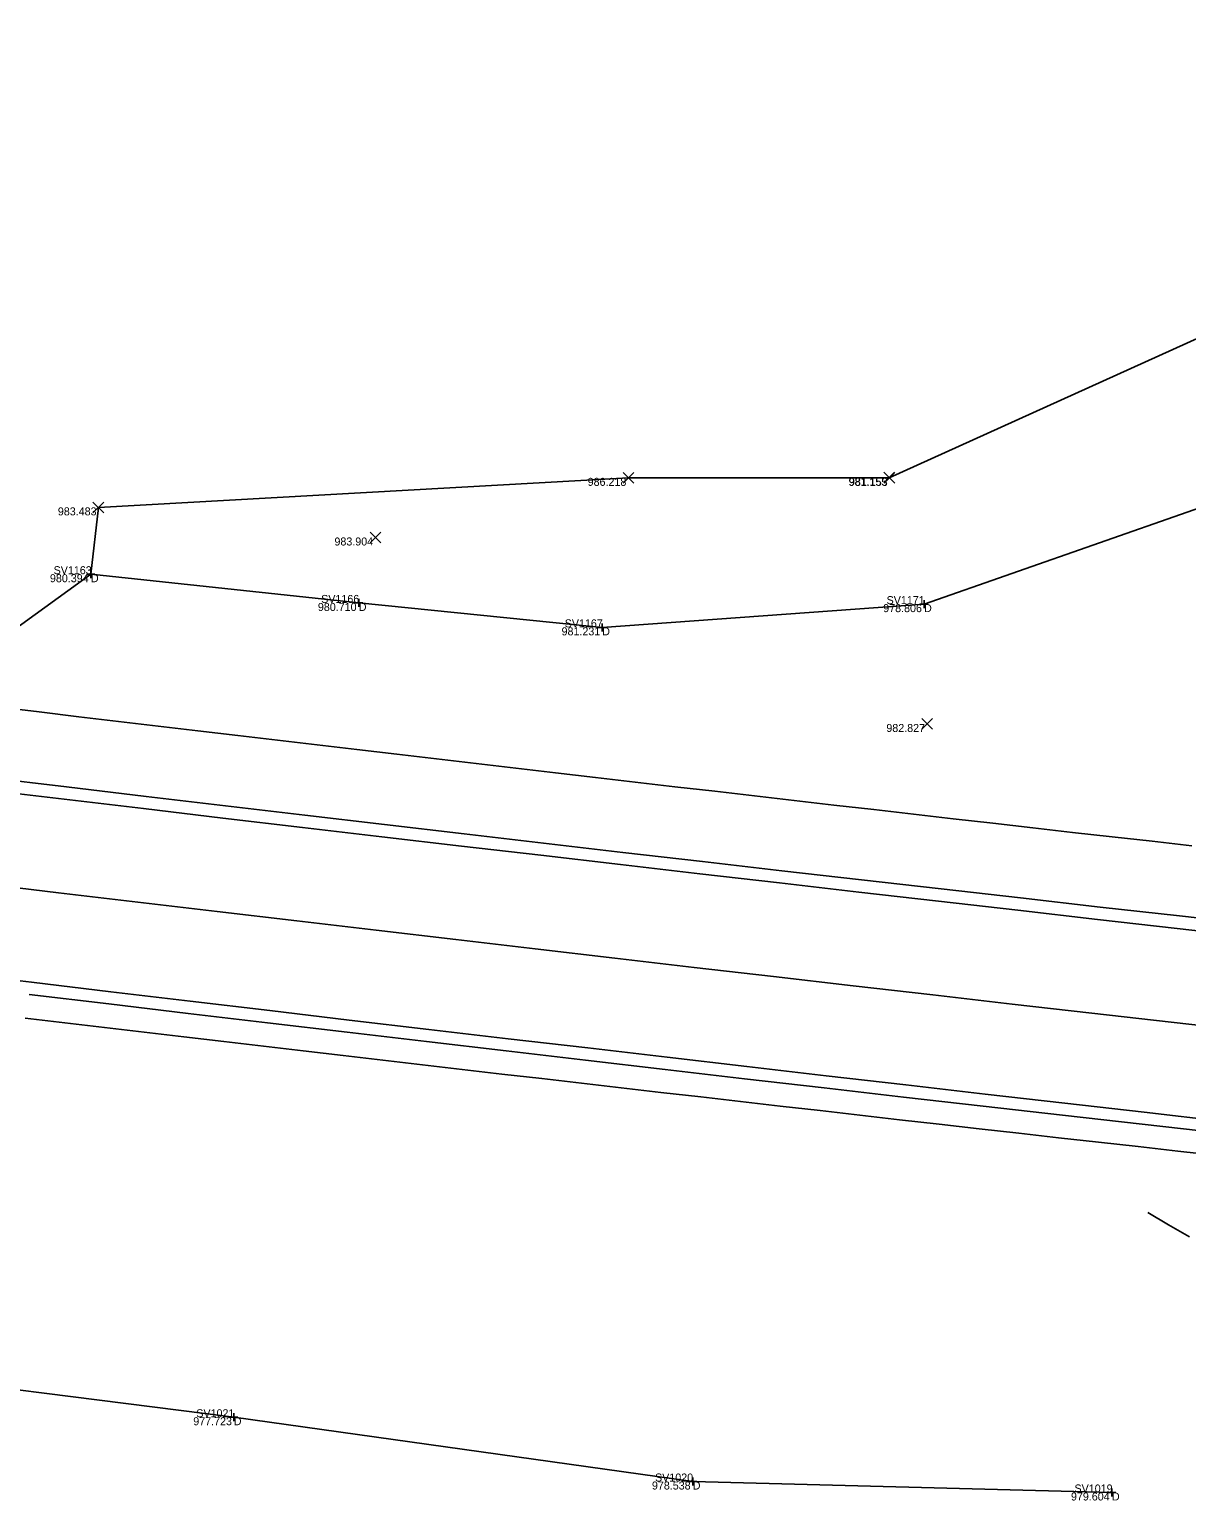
# Model space of a CAD drawing. Extents: x 2065431 to 2068157, y 709104 to 709719.
# Drawn here: x 2066972.9 to 2067117.5, y 709383.1 to 709566.9 of the extents above; entities that cross this region are included whole.
import ezdxf

# ---------------------------------------------------------------- set-up
doc = ezdxf.new("R2010")
doc.units = 0
for name, color, linetype in [('DT_X_Terrain_Boundary', 7, 'Continuous'), ('PM_X_Edge_Line', 7, 'Continuous'), ('PM_X_Lane_Line', 7, 'Continuous'), ('PV_X_EOP', 7, 'Continuous'), ('PV_X_Shoulder_Rumble_Strip', 7, 'Continuous'), ('RS_Raster1', 7, 'Continuous'), ('RW_X_CL_100_Bearings', 7, 'Continuous'), ('RW_X_Fee_WL', 7, 'Continuous'), ('SV_X_Mon_Cells_Found', 7, 'Continuous'), ('SV_X_Text_Elevation', 7, 'Continuous'), ('SV_X_Text_Name', 7, 'Continuous')]:
    doc.layers.add(name, color=color, linetype=linetype)

msp = doc.modelspace()

# ---------------------------------------------------------------- linework, layer by layer
at = {"layer": 'DT_X_Terrain_Boundary'}
msp.add_lwpolyline([(2067144.2, 709539.81), (2067080.32, 709510.92), (2067047.75, 709510.9), (2066981.51, 709507.21), (2066980.58, 709498.86), (2066959.21, 709483.43)], dxfattribs=at)
at = {"layer": 'PM_X_Edge_Line'}
for points in [[(2066967.29, 709471.93), (2066977.22, 709470.75), (2066987.15, 709469.57), (2066997.08, 709468.4), (2067007.01, 709467.22), (2067016.95, 709466.06), (2067026.88, 709464.9), (2067036.81, 709463.74), (2067046.74, 709462.58), (2067056.68, 709461.43), (2067066.61, 709460.29), (2067076.55, 709459.14), (2067086.48, 709458), (2067096.42, 709456.87), (2067106.35, 709455.74), (2067116.29, 709454.61), (2067126.22, 709453.49)], [(2066963.21, 709449.06), (2066973.14, 709447.87), (2066983.07, 709446.69), (2066993, 709445.51), (2067002.93, 709444.33), (2067012.86, 709443.16), (2067022.79, 709441.99), (2067032.72, 709440.83), (2067042.66, 709439.67), (2067052.59, 709438.51), (2067062.52, 709437.35), (2067072.46, 709436.2), (2067082.39, 709435.05), (2067092.32, 709433.91), (2067102.26, 709432.77), (2067112.19, 709431.63), (2067122.13, 709430.5)]]:
    msp.add_lwpolyline(points, dxfattribs=at)
at = {"layer": 'PM_X_Lane_Line'}
msp.add_lwpolyline([(2066966.58, 709460.24), (2066976.51, 709459.06), (2066986.44, 709457.88), (2066996.37, 709456.71), (2067006.3, 709455.54), (2067016.23, 709454.37), (2067026.16, 709453.21), (2067036.09, 709452.05), (2067046.03, 709450.89), (2067055.96, 709449.74), (2067065.89, 709448.59), (2067075.83, 709447.44), (2067085.76, 709446.3), (2067095.7, 709445.16), (2067105.63, 709444.02), (2067115.57, 709442.89), (2067125.5, 709441.77)], dxfattribs=at)
at = {"layer": 'PV_X_EOP'}
for points in [[(2066969.14, 709482.24), (2066974.1, 709481.65), (2066979.07, 709481.06), (2066984.03, 709480.47), (2066989, 709479.88), (2066993.96, 709479.29), (2066998.93, 709478.7), (2067003.89, 709478.12), (2067008.86, 709477.53), (2067013.82, 709476.95), (2067018.79, 709476.36), (2067023.76, 709475.78), (2067028.72, 709475.2), (2067033.69, 709474.62), (2067038.65, 709474.04), (2067043.62, 709473.46), (2067048.59, 709472.89), (2067053.55, 709472.31), (2067058.52, 709471.74), (2067063.49, 709471.16), (2067068.46, 709470.59), (2067073.42, 709470.02), (2067078.39, 709469.45), (2067083.36, 709468.88), (2067088.33, 709468.31), (2067093.29, 709467.74), (2067098.26, 709467.18), (2067103.23, 709466.61), (2067108.2, 709466.05), (2067113.17, 709465.49), (2067118.13, 709464.92)], [(2066972.35, 709443.41), (2066977.32, 709442.82), (2066982.28, 709442.23), (2066987.25, 709441.65), (2066992.21, 709441.06), (2066997.18, 709440.47), (2067002.14, 709439.89), (2067007.11, 709439.31), (2067012.08, 709438.73), (2067017.04, 709438.15), (2067022.01, 709437.57), (2067026.97, 709436.99), (2067031.94, 709436.41), (2067036.91, 709435.84), (2067041.88, 709435.26), (2067046.84, 709434.69), (2067051.81, 709434.12), (2067056.78, 709433.55), (2067061.74, 709432.98), (2067066.71, 709432.41), (2067071.68, 709431.84), (2067076.65, 709431.27), (2067081.61, 709430.71), (2067086.58, 709430.14), (2067091.55, 709429.58), (2067096.52, 709429.02), (2067101.49, 709428.46), (2067106.46, 709427.9), (2067111.43, 709427.34), (2067116.39, 709426.78), (2067121.36, 709426.22)], [(2067112.65, 709419.1), (2067115.24, 709417.59), (2067117.83, 709416.08)]]:
    msp.add_lwpolyline(points, dxfattribs=at)
at = {"layer": 'PV_X_Shoulder_Rumble_Strip'}
for points in [[(2066967.61, 709473.47), (2066977.54, 709472.28), (2066987.47, 709471.1), (2066997.4, 709469.93), (2067007.33, 709468.76), (2067017.26, 709467.59), (2067027.2, 709466.43), (2067037.13, 709465.27), (2067047.06, 709464.11), (2067057, 709462.96), (2067066.93, 709461.82), (2067076.86, 709460.68), (2067086.8, 709459.54), (2067096.74, 709458.41), (2067106.67, 709457.28), (2067116.61, 709456.16), (2067126.55, 709455.04)], [(2066972.87, 709446.35), (2066982.8, 709445.17), (2066992.73, 709443.98), (2067002.66, 709442.81), (2067012.59, 709441.64), (2067022.53, 709440.47), (2067032.46, 709439.3), (2067042.39, 709438.14), (2067052.32, 709436.99), (2067062.26, 709435.83), (2067072.19, 709434.69), (2067082.12, 709433.54), (2067092.06, 709432.4), (2067101.99, 709431.27), (2067111.93, 709430.13), (2067121.87, 709429.01)]]:
    msp.add_lwpolyline(points, dxfattribs=at)
at = {"layer": 'RS_Raster1'}
for p, q in [((2066980.08, 709498.86), (2066981.08, 709498.86)), ((2066980.58, 709499.36), (2066980.58, 709498.36)), ((2066980.58, 709498.86), (2066980.58, 709498.86)), ((2067013.55, 709495.27), (2067014.55, 709495.27)), ((2067014.05, 709495.77), (2067014.05, 709494.77)), ((2067014.05, 709495.27), (2067014.05, 709495.27)), ((2067084.18, 709495.12), (2067085.18, 709495.12)), ((2067084.68, 709495.62), (2067084.68, 709494.62)), ((2067084.68, 709495.12), (2067084.68, 709495.12)), ((2067044.47, 709492.72), (2067044.47, 709491.72)), ((2067043.97, 709492.22), (2067044.97, 709492.22)), ((2067044.47, 709492.22), (2067044.47, 709492.22)), ((2066997.93, 709393.53), (2066998.93, 709393.53)), ((2066998.43, 709394.03), (2066998.43, 709393.03)), ((2066998.43, 709393.53), (2066998.43, 709393.53)), ((2067055.78, 709386), (2067055.78, 709385)), ((2067055.28, 709385.5), (2067056.28, 709385.5)), ((2067055.78, 709385.5), (2067055.78, 709385.5)), ((2067107.66, 709384.13), (2067108.66, 709384.13)), ((2067108.16, 709384.63), (2067108.16, 709383.63)), ((2067108.16, 709384.13), (2067108.16, 709384.13))]:
    msp.add_line(p, q, dxfattribs=at)
at = {"layer": 'RW_X_CL_100_Bearings'}
for p, q in [((2067047.09, 709510.23), (2067048.42, 709511.57)), ((2067047.09, 709511.57), (2067048.42, 709510.23)), ((2067079.66, 709510.26), (2067080.99, 709511.59)), ((2067079.66, 709511.59), (2067080.99, 709510.26)), ((2067079.7, 709510.23), (2067081.03, 709511.56)), ((2067079.7, 709511.56), (2067081.03, 709510.23)), ((2066980.84, 709506.55), (2066982.18, 709507.88)), ((2066980.84, 709507.88), (2066982.18, 709506.55)), ((2067015.46, 709502.78), (2067016.8, 709504.11)), ((2067015.46, 709504.11), (2067016.8, 709502.78)), ((2067084.4, 709479.49), (2067085.73, 709480.82)), ((2067084.4, 709480.82), (2067085.73, 709479.49))]:
    msp.add_line(p, q, dxfattribs=at)
at = {"layer": 'RW_X_Fee_WL'}
for points in [[(2066980.58, 709498.86), (2067014.05, 709495.27), (2067044.47, 709492.22), (2067084.68, 709495.12), (2067150.43, 709518.1), (2067209.39, 709551.71), (2067238.49, 709566.93)], [(2067108.16, 709384.13), (2067055.78, 709385.5), (2066998.43, 709393.53), (2066947.7, 709399.97)]]:
    msp.add_lwpolyline(points, dxfattribs=at)

# ---------------------------------------------------------------- texts
at = {"layer": 'SV_X_Mon_Cells_Found'}
for s, p in [('SV1163', (2066975.92, 709498.86)), ('SV1166', (2067009.35, 709495.27)), ('SV1171', (2067080, 709495.12)), ('SV1167', (2067039.78, 709492.22)), ('SV1021', (2066993.75, 709393.53)), ('SV1020', (2067051.07, 709385.5)), ('SV1019', (2067103.48, 709384.13))]:
    msp.add_text(s, height=1, dxfattribs=at).set_placement(p)
at = {"layer": 'SV_X_Text_Elevation'}
for p in [(2066980.58, 709497.86), (2067014.05, 709494.27), (2067084.68, 709494.12), (2067044.47, 709491.22), (2066998.43, 709392.53), (2067055.78, 709384.5), (2067108.16, 709383.13)]:
    msp.add_text('D', height=1, dxfattribs=at).set_placement(p)
at = {"layer": 'SV_X_Text_Name'}
for s, p in [('986.218', (2067042.65, 709509.9)), ('981.155', (2067075.25, 709509.92)), ('981.153', (2067075.3, 709509.89)), ('983.483', (2066976.45, 709506.21)), ('983.904', (2067011.01, 709502.45)), ('980.394', (2066975.46, 709497.86)), ('980.710', (2067008.94, 709494.27)), ('978.806', (2067079.58, 709494.12)), ('981.231', (2067039.39, 709491.22)), ('982.827', (2067079.97, 709479.15)), ('977.723', (2066993.37, 709392.53)), ('978.538', (2067050.68, 709384.5)), ('979.604', (2067103.04, 709383.13))]:
    msp.add_text(s, height=1, dxfattribs=at).set_placement(p)

doc.saveas('drawing.dxf')
